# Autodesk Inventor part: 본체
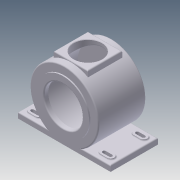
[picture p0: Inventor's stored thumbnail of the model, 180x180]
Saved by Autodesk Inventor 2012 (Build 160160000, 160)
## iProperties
Created: 2015-06
Part Number: 본체
Material: 알루미늄-6061
Document SubType Name: Modeling
Designer: User
Density: 2.71 g/cm^3
Mass: 3145.71 g
Surface Area: 2306.58 cm^2
Volume: 1160.78 cm^3
Author: User
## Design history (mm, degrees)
sketch "스케치4"
  geometry: L1 (-67, 0)-(67, 0); L2 (-67, 0)-(-67, 65); L3 (-67, 65)-(-54, 65); L4 (-54, 65)-(-54, 85); L5 (-54, 85)-(64, 85); L6 (64, 85)-(64, 65); L7 (64, 65)-(67, 65); L8 (67, 65)-(67, 47.5); L9 (67, 47.5)-(56, 47.5); L10 (56, 47.5)-(56, 77); L11 (56, 77)-(-46, 77); L12 (-46, 77)-(-46, 31); L13 (-46, 31)-(-42.5, 29.368); L14 (-42.5, 29.368)-(-42.5, 23.5); L15 (-42.5, 23.5)-(-56.5, 23.5); L16 (-56.5, 23.5)-(-56.5, 15); L17 (-56.5, 15)-(-59.5, 15); L18 (-59.5, 15)-(-59.5, 0); 3 further points
  constraints: 36 end point, 11 parallel, 5 perpendicular, 2 midpoint, 2 vertical alignment, 1 coincident, 1 horizontal, 1 point on line
  dimensions: "d9" = 134 distance of L1.start L1.end; "d11" = 30 diameter of L17 L1; "d12" = 3 distance of L16.end L17.end; "d13" = 14 distance of L14.end L15.end; "d14" = 47 diameter of L15 L1; "d15" = 115 deg angle of L12 L13; "d16" = 3.5 distance between parallel lines of L14 L12; "d17" = 62 diameter of L12.end L1; "d18" = 130 diameter of L3 L1; "d19" = 13 distance of L2.end L3.end; "d21" = 118 distance of L4.end L5.end; "d22" = 170 diameter of L5 L1; "d23" = 95 diameter of L9 L1; "d24" = 130 diameter of L7.end L1; "d25" = 154 diameter of L11 L1; "d26" = 102 distance of L10.end L11.end; "d27" = 7.5 distance between parallel lines of L2 L18
revolve "회전1" sketch "스케치4" stored, may be unused: angle "d28" = 90 deg
node "작업 평면1"
sketch "스케치5"
  geometry: L1 (-64, 115)-(54, 115); L2 (54, 115)-(54, -115); L3 (54, -115)-(-64, -115); L4 (-64, -115)-(-64, 115); L5 (-64, 85)-(-64, -85) reference; L6 (54, 85)-(54, -85) reference; 3 further points
  constraints: 8 end point, 3 midpoint, 2 parallel, 1 horizontal, 1 horizontal alignment, 1 perpendicular
  dimensions: "d30" = 118 distance of L1.start L1.end; "d31" = 230 distance of L3.end L1.start
extrude "돌출4" join sketch "스케치5" distance "d32" = 8; taper "d33" = 0 deg
extrude "돌출5" join sketch "스케치5" distance "d34" = 6; taper "d35" = 0 deg
sketch "스케치6"
  geometry: L1 (56, 71)-(-46, 71) reference; L2 (-46, 71)-(-46, 71) reference; L3 (-46, 71)-(56, 71) reference; L4 (56, 71)-(56, 71) reference; L5 (56, -77)-(-46, -77) reference; L6 (56, -77)-(56, 71) reference; L7 (-46, -77)-(-46, 71) reference; L8 (-59, 0)-(59, 0); L9 (-46, -77)-(56, -77); L10 (56, -69)-(-46, -69); L11 (-46, -77)-(-46, -69); 2 further points
  constraints: 8 end point, 3 perpendicular, 2 point on line, 1 coincident, 1 collinear, 1 midpoint
  dimensions: "d36" = 118 distance of L8.start L8.end; "d37" = 8 distance of L5.end L10.end
revolve "회전2" sketch "스케치6" stored, may be unused: angle "d38" = 90 deg
node "작업 평면2"
sketch "스케치7"
  geometry: L1 (64, 115)-(-54, 115) reference; L2 (-54, 115)-(-54, 46.733) reference; L3 (64, 46.733)-(64, 115) reference; L4 (64, -115)-(64, -46.733) reference; L5 (-54, -115)-(64, -115) reference; L6 (-54, -46.733)-(-54, -115) reference; L7 (-40, -81)-(-40, -97); L8 (-32, -81)-(-32, -97); L9 (-45, -97)-(-45, -81); L10 (-27, -81)-(-27, -97); A1 r 4 centre (-36, -81) between (-32, -81) and (-40, -81); A2 r 4 centre (-36, -97) between (-40, -97) and (-32, -97); A3 r 9 centre (-36, -81) between (-27, -81) and (-45, -81); A4 r 9 centre (-36, -97) between (-45, -97) and (-27, -97); 1 further point
  constraints: 8 end point, 8 point on circle, 4 centre point, 3 tangent, 2 parallel, 1 vertical alignment, 3 other
  dimensions: "d40" = 8 diameter of A1; "d41" = 8 diameter of A2; "d42" = 16 distance of A2.centre A1.centre; "d43" = 18 distance between parallel lines of L10 L9; "d44" = 18 distance from line of L6 A2.centre; "d45" = 18 distance from line of L5 A2.centre
extrude "돌출6" join sketch "스케치7" stored distance "d46" = 6; taper "d47" = 0 deg
extrude "돌출7" cut sketch "스케치7" stored distance "d48" = 6; taper "d49" = 0 deg
fillet "모깎기1" dims "d53" = 0.3
fillet "모깎기2" dims "d54" = 3
fillet "모깎기3" dims "d55" = 3
fillet "모깎기4" dims "d56" = 3
node "작업 평면4"
sketch "스케치9"
  geometry: L1 (-51, -85)-(61, -85) reference; L2 (-51, 85)-(61, 85) reference; L3 (5, -85)-(5, 85); L4 (-37.5, -42.5)-(47.5, -42.5); L5 (47.5, -42.5)-(47.5, 42.5); L6 (47.5, 42.5)-(-37.5, 42.5); L7 (-37.5, 42.5)-(-37.5, -42.5); C1 r 35 at (5, 0); 3 further points
  constraints: 10 end point, 5 midpoint, 2 parallel, 1 centre point, 1 horizontal, 1 horizontal alignment, 1 perpendicular, 1 vertical alignment
  dimensions: "d62" = 70 diameter of C1; "d63" = 85 distance of L4.start L4.end; "d64" = 85 distance of L4.end L5.end; "d65" = 85 distance from line of L1 C1.centre (derived)
extrude "돌출8" join sketch "스케치9" stored distance "d66" = 6; taper "d67" = 0 deg
extrude "돌출9" cut sketch "스케치9" stored distance "d68" = 6; taper "d69" = 0 deg
fillet "모깎기5" dims "d70" = 3
fillet "모깎기6" dims "d71" = 3
chamfer "모따기1" distance "d72" = 1; stored, may be unused: second distance "d73" = 2, angle "d74" = 45 deg
node "솔리드2"
pattern_linear "직사각형 패턴1" dims "d52" = 82
mirror "대칭1"
node "투영된 루프1"
other parameters: "d29" = 77, "d39" = -17, "d61" = -173
